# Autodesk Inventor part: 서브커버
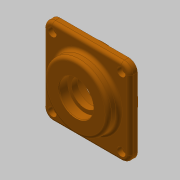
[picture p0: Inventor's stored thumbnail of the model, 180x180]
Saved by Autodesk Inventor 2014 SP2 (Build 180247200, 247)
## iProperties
Created: 2018-09
Part Number: 서브커버
Material: 알루미늄 6061
Document SubType Name: Modeling
Designer: mduedu
Density: 1 g/cm^3
Appearance: 주황색
Author: mduedu
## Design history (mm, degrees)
sketch "스케치1"
  geometry: L1 (-40, -40)-(40, -40); L2 (40, -40)-(40, 40); L3 (40, 40)-(-40, 40); L4 (-40, 40)-(-40, -40); L5 (-40, -40)-(40, 40); L6 (40, -40)-(-40, 40); 1 further point
  constraints: 12 end point, 2 midpoint, 2 parallel, 1 horizontal, 1 perpendicular
  dimensions: "d0" = 80 distance of L3.end L2.end; "d1" = 80 distance of L2.end L1.end
extrude "돌출1" new body sketch "스케치1" distance "d2" = 7; taper "d3" = 0 deg
sketch "스케치2"
  geometry: C1 r 30 at (0, 0); 1 further point
  constraints: 1 centre point, 1 coincident
  dimensions: "d4" = 60 diameter of C1
extrude "돌출2" join sketch "스케치2" distance "d5" = 10; taper "d6" = 0 deg
sketch "스케치3"
  geometry: C1 r 32.5 at (0, 0); 1 further point
  constraints: 1 centre point, 1 coincident
  dimensions: "d7" = 65 diameter of C1
extrude "돌출3" join sketch "스케치3" distance "d8" = 9; taper "d9" = 0 deg
sketch "스케치4"
  geometry: L1 (-32.5, -9)-(32.5, -9) reference; L2 (30, 17)-(-30, 17) reference; L3 (0, 17)-(0, -9); L4 (0, -9)-(20, -9); L5 (20, -9)-(20, 3); L6 (20, 3)-(0, 3); L7 (0, 3)-(0, -9); L8 (0, 3)-(12.5, 3); L9 (12.5, 3)-(12.5, 8.7); L10 (12.5, 8.7)-(0, 8.7); L11 (0, 8.7)-(0, 3); L12 (0, 8.7)-(16, 8.7); L13 (16, 8.7)-(16, 17); L14 (16, 17)-(0, 17); L15 (0, 17)-(0, 8.7); 1 further point
  constraints: 26 end point, 6 parallel, 3 horizontal, 3 perpendicular, 2 midpoint, 1 point on line
  dimensions: "d10" = 12 distance of L4.end L5.end; "d12" = 8.3 distance of L12.end L13.end; "d13" = 32 diameter of L13 L3; "d14" = 25 diameter of L9 L3; "d15" = 40 diameter of L5 L3
revolve "회전1" sketch "스케치4" stored, may be unused: angle "d16" = 90 deg
fillet "모깎기1" dims "d17" = 8
fillet "모깎기2" dims "d18" = 3
fillet "모깎기3" dims "d19" = 3
chamfer "모따기1" distance "d20" = 0.8; stored, may be unused: second distance "d21" = 2, angle "d22" = 30 deg
chamfer "모따기2" distance "d23" = 1; stored, may be unused: second distance "d24" = 2, angle "d25" = 30 deg
fillet "모깎기4" dims "d26" = 0.3
sketch "스케치5"
  geometry: A1 r 8 centre (-32, 32) between (-32, 40) and (-40, 32) reference; A2 r 8 centre (-32, -32) between (-40, -32) and (-32, -40) reference; A3 r 8 centre (32, -32) between (32, -40) and (40, -32) reference; A4 r 8 centre (32, 32) between (40, 32) and (32, 40) reference; 5 further points
  constraints: 4 coincident
hole "구멍1" sketch "스케치5" at (-32, 32), (32, 32), (32, -32), (-32, -32) diameter "d27" = 4.5; stored, may be unused: countersink angle "d31" = 90 deg, drill point angle "d33" = 118 deg; dims "d28" = 6, "d29" = 8, "d30" = 4.4, "d32" = 8
node "솔리드1"
